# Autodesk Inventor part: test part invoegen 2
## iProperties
Created: 2009-12
Part Number: test part invoegen 2
Document SubType Name: Modeling
Designer: Guido
Mass: 1.1781 g
Surface Area: 6.28319 cm^2
Volume: 1.1781 cm^3
Density: 1 g/cm^3
Description: Part aan of uit
Author: Guido
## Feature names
1. Extrusion1
